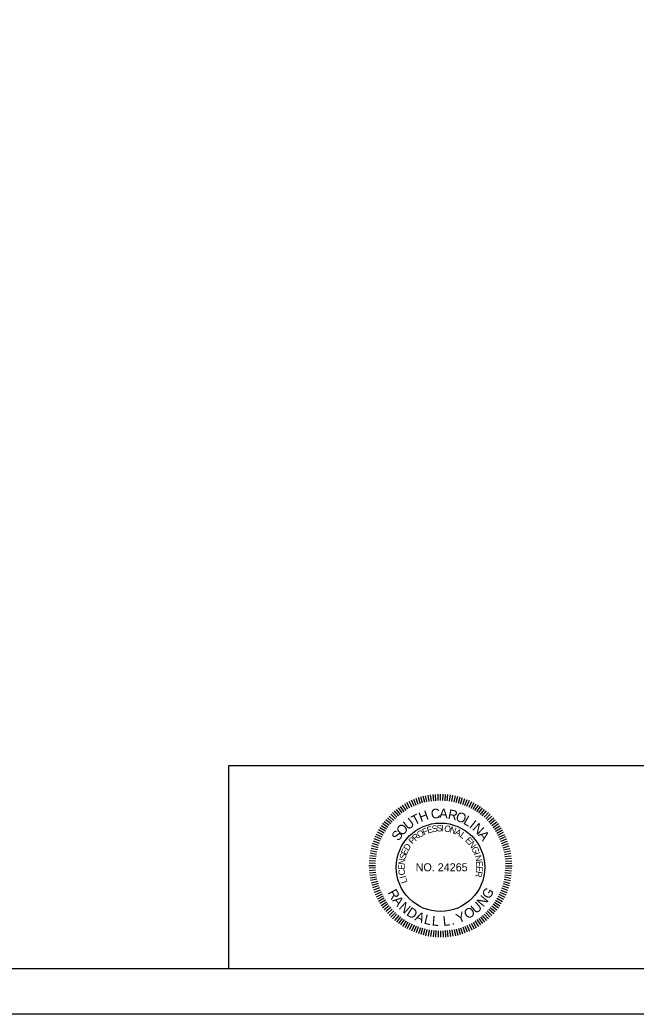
# Model space of a CAD drawing. Extents: x -796 to 2793, y -4650 to 4425.
# Drawn here: x 1879 to 2221, y -3500 to -2950 of the extents above; entities that cross this region are included whole.
import ezdxf

# ---------------------------------------------------------------- set-up
doc = ezdxf.new("R2010")
doc.units = 0
for name, color, linetype in [('RD_HC_CL', 7, 'Continuous'), ('RD_HC_Data', 7, 'Continuous'), ('RD_TX_PEShield', 7, 'Continuous')]:
    doc.layers.add(name, color=color, linetype=linetype)

msp = doc.modelspace()

# ---------------------------------------------------------------- linework, layer by layer
at = {"layer": 'RD_HC_CL'}
msp.add_lwpolyline([(981.4, -2400), (2777.4, -2400), (2777.4, -3500), (981.4, -3500)], close=True, dxfattribs=at)
at = {"layer": 'RD_HC_Data'}
for p, q in [((1995.01, -3362.55), (2757.6, -3362.55)), ((1995.01, -3475), (1995.01, -3362.55)), ((2760, -3500), (1000, -3500)), ((2760, -3500), (1000, -3500))]:
    msp.add_line(p, q, dxfattribs=at)
msp.add_lwpolyline([(1082.6, -2425), (2757.6, -2425), (2757.6, -3475), (1082.6, -3475)], close=True, dxfattribs=at)
at = {"layer": 'RD_TX_PEShield'}
for p, q in [((2096.52, -3385.54), (2094.96, -3382.34)), ((2096.52, -3385.54), (2094.96, -3382.34)), ((2097.64, -3384.97), (2096.19, -3381.71)), ((2097.64, -3384.97), (2096.19, -3381.71)), ((2098.81, -3384.52), (2097.48, -3381.22)), ((2098.81, -3384.52), (2097.48, -3381.22)), ((2099.98, -3384.07), (2098.77, -3380.72)), ((2099.98, -3384.07), (2098.77, -3380.72)), ((2101.16, -3383.62), (2100.06, -3380.23)), ((2101.16, -3383.62), (2100.06, -3380.23)), ((2102.37, -3383.29), (2101.39, -3379.87)), ((2102.37, -3383.29), (2101.39, -3379.87)), ((2103.59, -3382.96), (2102.73, -3379.51)), ((2103.59, -3382.96), (2102.73, -3379.51)), ((2104.8, -3382.64), (2104.06, -3379.16)), ((2104.8, -3382.64), (2104.06, -3379.16)), ((2106.05, -3382.44), (2105.43, -3378.94)), ((2106.05, -3382.44), (2105.43, -3378.94)), ((2107.29, -3382.25), (2106.79, -3378.72)), ((2107.29, -3382.25), (2106.79, -3378.72)), ((2108.53, -3382.05), (2108.16, -3378.51)), ((2108.53, -3382.05), (2108.16, -3378.51)), ((2109.79, -3381.98), (2109.54, -3378.44)), ((2109.79, -3381.98), (2109.54, -3378.44)), ((2111.04, -3381.92), (2110.92, -3378.36)), ((2111.04, -3381.92), (2110.92, -3378.36)), ((2112.3, -3381.85), (2112.3, -3378.29)), ((2112.3, -3381.85), (2112.3, -3378.29)), ((2113.55, -3381.92), (2113.68, -3378.36)), ((2113.55, -3381.92), (2113.68, -3378.36)), ((2114.81, -3381.98), (2115.06, -3378.44)), ((2114.81, -3381.98), (2115.06, -3378.44)), ((2116.07, -3382.05), (2116.44, -3378.51)), ((2116.07, -3382.05), (2116.44, -3378.51)), ((2117.31, -3382.25), (2117.8, -3378.72)), ((2117.31, -3382.25), (2117.8, -3378.72)), ((2118.55, -3382.44), (2119.17, -3378.94)), ((2118.55, -3382.44), (2119.17, -3378.94)), ((2119.79, -3382.64), (2120.53, -3379.16)), ((2119.79, -3382.64), (2120.53, -3379.16)), ((2119.79, -3382.64), (2120.53, -3379.16)), ((2121.01, -3382.96), (2121.87, -3379.51)), ((2121.01, -3382.96), (2121.87, -3379.51)), ((2121.01, -3382.96), (2121.87, -3379.51)), ((2122.22, -3383.29), (2123.2, -3379.87)), ((2122.22, -3383.29), (2123.2, -3379.87)), ((2122.22, -3383.29), (2123.2, -3379.87)), ((2123.44, -3383.62), (2124.54, -3380.23)), ((2123.44, -3383.62), (2124.54, -3380.23)), ((2123.44, -3383.62), (2124.54, -3380.23)), ((2124.61, -3384.07), (2125.83, -3380.72)), ((2124.61, -3384.07), (2125.83, -3380.72)), ((2124.61, -3384.07), (2125.83, -3380.72)), ((2125.78, -3384.52), (2127.12, -3381.22)), ((2125.78, -3384.52), (2127.12, -3381.22)), ((2125.78, -3384.52), (2127.12, -3381.22)), ((2126.96, -3384.97), (2128.41, -3381.71)), ((2126.96, -3384.97), (2128.41, -3381.71)), ((2126.96, -3384.97), (2128.41, -3381.71)), ((2128.08, -3385.54), (2129.64, -3382.34)), ((2128.08, -3385.54), (2129.64, -3382.34)), ((2128.08, -3385.54), (2129.64, -3382.34)), ((2089.16, -3390.32), (2086.87, -3387.59)), ((2089.16, -3390.32), (2086.87, -3387.59)), ((2090.13, -3389.53), (2087.94, -3386.72)), ((2090.13, -3389.53), (2087.94, -3386.72)), ((2091.11, -3388.73), (2089.02, -3385.85)), ((2091.11, -3388.73), (2089.02, -3385.85)), ((2092.17, -3388.05), (2090.18, -3385.1)), ((2092.17, -3388.05), (2090.18, -3385.1)), ((2093.22, -3387.37), (2091.34, -3384.35)), ((2093.22, -3387.37), (2091.34, -3384.35)), ((2094.28, -3386.68), (2092.5, -3383.6)), ((2094.28, -3386.68), (2092.5, -3383.6)), ((2095.4, -3386.11), (2093.73, -3382.97)), ((2095.4, -3386.11), (2093.73, -3382.97)), ((2129.2, -3386.11), (2130.87, -3382.97)), ((2129.2, -3386.11), (2130.87, -3382.97)), ((2129.2, -3386.11), (2130.87, -3382.97)), ((2130.32, -3386.68), (2132.1, -3383.6)), ((2130.32, -3386.68), (2132.1, -3383.6)), ((2130.32, -3386.68), (2132.1, -3383.6)), ((2131.38, -3387.37), (2133.26, -3384.35)), ((2131.38, -3387.37), (2133.26, -3384.35)), ((2131.38, -3387.37), (2133.26, -3384.35)), ((2132.43, -3388.05), (2134.42, -3385.1)), ((2132.43, -3388.05), (2134.42, -3385.1)), ((2132.43, -3388.05), (2134.42, -3385.1)), ((2133.48, -3388.73), (2135.58, -3385.85)), ((2133.48, -3388.73), (2135.58, -3385.85)), ((2133.48, -3388.73), (2135.58, -3385.85)), ((2134.46, -3389.53), (2136.65, -3386.72)), ((2134.46, -3389.53), (2136.65, -3386.72)), ((2134.46, -3389.53), (2136.65, -3386.72)), ((2135.44, -3390.32), (2137.72, -3387.59)), ((2135.44, -3390.32), (2137.72, -3387.59)), ((2135.44, -3390.32), (2137.72, -3387.59)), ((2084.72, -3394.75), (2082, -3392.47)), ((2084.72, -3394.75), (2082, -3392.47)), ((2085.51, -3393.78), (2082.87, -3391.4)), ((2085.51, -3393.78), (2082.87, -3391.4)), ((2086.4, -3392.89), (2083.84, -3390.42)), ((2086.4, -3392.89), (2083.84, -3390.42)), ((2087.29, -3392), (2084.82, -3389.44)), ((2087.29, -3392), (2084.82, -3389.44)), ((2088.18, -3391.11), (2085.8, -3388.46)), ((2088.18, -3391.11), (2085.8, -3388.46)), ((2136.42, -3391.11), (2138.8, -3388.46)), ((2136.42, -3391.11), (2138.8, -3388.46)), ((2136.42, -3391.11), (2138.8, -3388.46)), ((2137.31, -3392), (2139.78, -3389.44)), ((2137.31, -3392), (2139.78, -3389.44)), ((2137.31, -3392), (2139.78, -3389.44)), ((2138.2, -3392.89), (2140.75, -3390.42)), ((2138.2, -3392.89), (2140.75, -3390.42)), ((2138.2, -3392.89), (2140.75, -3390.42)), ((2139.08, -3393.78), (2141.73, -3391.4)), ((2139.08, -3393.78), (2141.73, -3391.4)), ((2139.08, -3393.78), (2141.73, -3391.4)), ((2139.88, -3394.75), (2142.6, -3392.47)), ((2139.88, -3394.75), (2142.6, -3392.47)), ((2139.88, -3394.75), (2142.6, -3392.47)), ((2081.08, -3399.87), (2078, -3398.09)), ((2081.08, -3399.87), (2078, -3398.09)), ((2081.77, -3398.82), (2078.75, -3396.93)), ((2081.77, -3398.82), (2078.75, -3396.93)), ((2082.45, -3397.76), (2079.5, -3395.78)), ((2082.45, -3397.76), (2079.5, -3395.78)), ((2083.14, -3396.71), (2080.26, -3394.62)), ((2083.14, -3396.71), (2080.26, -3394.62)), ((2083.93, -3395.73), (2081.13, -3393.54)), ((2083.93, -3395.73), (2081.13, -3393.54)), ((2140.67, -3395.73), (2143.47, -3393.54)), ((2140.67, -3395.73), (2143.47, -3393.54)), ((2140.67, -3395.73), (2143.47, -3393.54)), ((2141.46, -3396.71), (2144.34, -3394.62)), ((2141.46, -3396.71), (2144.34, -3394.62)), ((2141.46, -3396.71), (2144.34, -3394.62)), ((2142.14, -3397.76), (2145.09, -3395.78)), ((2142.14, -3397.76), (2145.09, -3395.78)), ((2142.14, -3397.76), (2145.09, -3395.78)), ((2142.83, -3398.82), (2145.84, -3396.93)), ((2142.83, -3398.82), (2145.84, -3396.93)), ((2142.83, -3398.82), (2145.84, -3396.93)), ((2143.51, -3399.87), (2146.6, -3398.09)), ((2143.51, -3399.87), (2146.6, -3398.09)), ((2143.51, -3399.87), (2146.6, -3398.09)), ((2078.47, -3405.58), (2075.13, -3404.37)), ((2078.47, -3405.58), (2075.13, -3404.37)), ((2078.92, -3404.41), (2075.62, -3403.08)), ((2078.92, -3404.41), (2075.62, -3403.08)), ((2079.37, -3403.24), (2076.12, -3401.79)), ((2079.37, -3403.24), (2076.12, -3401.79)), ((2079.94, -3402.11), (2076.74, -3400.56)), ((2079.94, -3402.11), (2076.74, -3400.56)), ((2080.51, -3400.99), (2077.37, -3399.33)), ((2080.51, -3400.99), (2077.37, -3399.33)), ((2144.09, -3400.99), (2147.22, -3399.33)), ((2144.09, -3400.99), (2147.22, -3399.33)), ((2144.09, -3400.99), (2147.22, -3399.33)), ((2144.66, -3402.11), (2147.85, -3400.56)), ((2144.66, -3402.11), (2147.85, -3400.56)), ((2144.66, -3402.11), (2147.85, -3400.56)), ((2145.23, -3403.24), (2148.48, -3401.79)), ((2145.23, -3403.24), (2148.48, -3401.79)), ((2145.23, -3403.24), (2148.48, -3401.79)), ((2145.68, -3404.41), (2148.97, -3403.08)), ((2145.68, -3404.41), (2148.97, -3403.08)), ((2145.68, -3404.41), (2148.97, -3403.08)), ((2146.13, -3405.58), (2149.47, -3404.37)), ((2146.13, -3405.58), (2149.47, -3404.37)), ((2146.13, -3405.58), (2149.47, -3404.37)), ((2077.04, -3410.4), (2073.56, -3409.66)), ((2077.04, -3410.4), (2073.56, -3409.66)), ((2077.37, -3409.19), (2073.92, -3408.33)), ((2077.37, -3409.19), (2073.92, -3408.33)), ((2077.69, -3407.97), (2074.27, -3406.99)), ((2077.69, -3407.97), (2074.27, -3406.99)), ((2078.02, -3406.76), (2074.63, -3405.66)), ((2078.02, -3406.76), (2074.63, -3405.66)), ((2146.58, -3406.76), (2149.96, -3405.66)), ((2146.58, -3406.76), (2149.96, -3405.66)), ((2146.58, -3406.76), (2149.96, -3405.66)), ((2146.9, -3407.97), (2150.32, -3406.99)), ((2146.9, -3407.97), (2150.32, -3406.99)), ((2146.9, -3407.97), (2150.32, -3406.99)), ((2147.23, -3409.19), (2150.68, -3408.33)), ((2147.23, -3409.19), (2150.68, -3408.33)), ((2147.23, -3409.19), (2150.68, -3408.33)), ((2147.56, -3410.4), (2151.04, -3409.66)), ((2147.56, -3410.4), (2151.04, -3409.66)), ((2147.56, -3410.4), (2151.04, -3409.66)), ((2076.38, -3415.38), (2072.84, -3415.14)), ((2076.38, -3415.38), (2072.84, -3415.14)), ((2076.45, -3414.13), (2072.91, -3413.76)), ((2076.45, -3414.13), (2072.91, -3413.76)), ((2076.65, -3412.89), (2073.13, -3412.39)), ((2076.65, -3412.89), (2073.13, -3412.39)), ((2076.84, -3411.64), (2073.34, -3411.03)), ((2076.84, -3411.64), (2073.34, -3411.03)), ((2147.75, -3411.64), (2151.25, -3411.03)), ((2147.75, -3411.64), (2151.25, -3411.03)), ((2147.75, -3411.64), (2151.25, -3411.03)), ((2147.95, -3412.89), (2151.47, -3412.39)), ((2147.95, -3412.89), (2151.47, -3412.39)), ((2147.95, -3412.89), (2151.47, -3412.39)), ((2148.15, -3414.13), (2151.69, -3413.76)), ((2148.15, -3414.13), (2151.69, -3413.76)), ((2148.15, -3414.13), (2151.69, -3413.76)), ((2148.21, -3415.38), (2151.76, -3415.14)), ((2148.21, -3415.38), (2151.76, -3415.14)), ((2148.21, -3415.38), (2151.76, -3415.14)), ((2076.25, -3417.9), (2072.69, -3417.9)), ((2076.25, -3417.9), (2072.69, -3417.9)), ((2076.32, -3416.64), (2072.77, -3416.52)), ((2076.32, -3416.64), (2072.77, -3416.52)), ((2076.32, -3419.15), (2072.77, -3419.28)), ((2076.32, -3419.15), (2072.77, -3419.28)), ((2076.38, -3420.41), (2072.84, -3420.66)), ((2076.38, -3420.41), (2072.84, -3420.66)), ((2148.08, -3420.4), (2151.61, -3420.65)), ((2148.08, -3420.4), (2151.61, -3420.65)), ((2148.21, -3419.15), (2151.76, -3419.27)), ((2148.21, -3419.15), (2151.76, -3419.27)), ((2148.28, -3416.64), (2151.83, -3416.52)), ((2148.28, -3416.64), (2151.83, -3416.52)), ((2148.28, -3416.64), (2151.83, -3416.52)), ((2148.34, -3417.9), (2151.9, -3417.9)), ((2148.34, -3417.9), (2151.9, -3417.9)), ((2148.34, -3417.9), (2151.9, -3417.9)), ((2076.45, -3421.66), (2072.91, -3422.04)), ((2076.45, -3421.66), (2072.91, -3422.04)), ((2076.65, -3422.91), (2073.13, -3423.4)), ((2076.65, -3422.91), (2073.13, -3423.4)), ((2076.84, -3424.15), (2073.34, -3424.76)), ((2076.84, -3424.15), (2073.34, -3424.76)), ((2077.04, -3425.39), (2073.56, -3426.13)), ((2077.04, -3425.39), (2073.56, -3426.13)), ((2147.56, -3425.39), (2151.04, -3426.13)), ((2147.56, -3425.39), (2151.04, -3426.13)), ((2147.69, -3424.14), (2151.18, -3424.75)), ((2147.69, -3424.14), (2151.18, -3424.75)), ((2147.82, -3422.89), (2151.33, -3423.38)), ((2147.82, -3422.89), (2151.33, -3423.38)), ((2147.95, -3421.64), (2151.47, -3422.01)), ((2147.95, -3421.64), (2151.47, -3422.01)), ((2077.37, -3426.61), (2073.92, -3427.47)), ((2077.37, -3426.61), (2073.92, -3427.47)), ((2077.69, -3427.82), (2074.27, -3428.8)), ((2077.69, -3427.82), (2074.27, -3428.8)), ((2078.02, -3429.03), (2074.63, -3430.13)), ((2078.47, -3430.21), (2075.13, -3431.43)), ((2078.47, -3430.21), (2075.13, -3431.43)), ((2078.92, -3431.38), (2075.62, -3432.71)), ((2078.92, -3431.38), (2075.62, -3432.71)), ((2145.68, -3431.38), (2148.97, -3432.71)), ((2145.68, -3431.38), (2148.97, -3432.71)), ((2146.13, -3430.21), (2149.47, -3431.43)), ((2146.13, -3430.21), (2149.47, -3431.43)), ((2146.58, -3429.03), (2149.96, -3430.13)), ((2146.58, -3429.03), (2149.96, -3430.13)), ((2146.9, -3427.82), (2150.32, -3428.8)), ((2146.9, -3427.82), (2150.32, -3428.8)), ((2147.23, -3426.61), (2150.68, -3427.47)), ((2147.23, -3426.61), (2150.68, -3427.47)), ((2079.37, -3432.56), (2076.12, -3434)), ((2079.37, -3432.56), (2076.12, -3434)), ((2079.94, -3433.68), (2076.74, -3435.24)), ((2079.94, -3433.68), (2076.74, -3435.24)), ((2080.51, -3434.8), (2077.37, -3436.47)), ((2080.51, -3434.8), (2077.37, -3436.47)), ((2081.08, -3435.92), (2078, -3437.7)), ((2081.08, -3435.92), (2078, -3437.7)), ((2081.77, -3436.97), (2078.75, -3438.86)), ((2081.77, -3436.97), (2078.75, -3438.86)), ((2142.83, -3436.97), (2145.84, -3438.86)), ((2142.83, -3436.97), (2145.84, -3438.86)), ((2143.51, -3435.92), (2146.6, -3437.7)), ((2143.51, -3435.92), (2146.6, -3437.7)), ((2144.09, -3434.8), (2147.22, -3436.47)), ((2144.09, -3434.8), (2147.22, -3436.47)), ((2144.66, -3433.68), (2147.85, -3435.24)), ((2144.66, -3433.68), (2147.85, -3435.24)), ((2145.23, -3432.56), (2148.48, -3434)), ((2145.23, -3432.56), (2148.48, -3434)), ((2082.45, -3438.03), (2079.5, -3440.02)), ((2082.45, -3438.03), (2079.5, -3440.02)), ((2083.14, -3439.08), (2080.26, -3441.18)), ((2083.14, -3439.08), (2080.26, -3441.18)), ((2083.93, -3440.06), (2081.13, -3442.25)), ((2083.93, -3440.06), (2081.13, -3442.25)), ((2084.72, -3441.04), (2082, -3443.32)), ((2084.72, -3441.04), (2082, -3443.32)), ((2085.51, -3442.01), (2082.87, -3444.4)), ((2085.51, -3442.01), (2082.87, -3444.4)), ((2086.4, -3442.9), (2083.84, -3445.37)), ((2086.4, -3442.9), (2083.84, -3445.37)), ((2138.2, -3442.9), (2140.75, -3445.37)), ((2138.2, -3442.9), (2140.75, -3445.37)), ((2139.08, -3442.01), (2141.73, -3444.4)), ((2139.08, -3442.01), (2141.73, -3444.4)), ((2139.88, -3441.04), (2142.6, -3443.32)), ((2139.88, -3441.04), (2142.6, -3443.32)), ((2140.67, -3440.06), (2143.47, -3442.25)), ((2140.67, -3440.06), (2143.47, -3442.25)), ((2141.46, -3439.08), (2144.34, -3441.18)), ((2141.46, -3439.08), (2144.34, -3441.18)), ((2142.14, -3438.03), (2145.09, -3440.02)), ((2142.14, -3438.03), (2145.09, -3440.02)), ((2087.29, -3443.79), (2084.82, -3446.35)), ((2087.29, -3443.79), (2084.82, -3446.35)), ((2088.18, -3444.68), (2085.8, -3447.33)), ((2088.18, -3444.68), (2085.8, -3447.33)), ((2089.16, -3445.47), (2086.87, -3448.2)), ((2089.16, -3445.47), (2086.87, -3448.2)), ((2090.13, -3446.27), (2087.94, -3449.07)), ((2090.13, -3446.27), (2087.94, -3449.07)), ((2091.11, -3447.06), (2089.02, -3449.94)), ((2091.11, -3447.06), (2089.02, -3449.94)), ((2092.17, -3447.74), (2090.18, -3450.69)), ((2092.17, -3447.74), (2090.18, -3450.69)), ((2093.22, -3448.43), (2091.34, -3451.44)), ((2093.22, -3448.43), (2091.34, -3451.44)), ((2131.38, -3448.43), (2133.26, -3451.44)), ((2131.38, -3448.43), (2133.26, -3451.44)), ((2132.43, -3447.74), (2134.42, -3450.69)), ((2132.43, -3447.74), (2134.42, -3450.69)), ((2133.48, -3447.06), (2135.58, -3449.94)), ((2133.48, -3447.06), (2135.58, -3449.94)), ((2134.46, -3446.27), (2136.65, -3449.07)), ((2134.46, -3446.27), (2136.65, -3449.07)), ((2135.44, -3445.47), (2137.72, -3448.2)), ((2135.44, -3445.47), (2137.72, -3448.2)), ((2136.42, -3444.68), (2138.8, -3447.33)), ((2137.31, -3443.79), (2139.78, -3446.35)), ((2137.31, -3443.79), (2139.78, -3446.35)), ((2094.28, -3449.11), (2092.5, -3452.19)), ((2094.28, -3449.11), (2092.5, -3452.19)), ((2095.4, -3449.68), (2093.73, -3452.82)), ((2095.4, -3449.68), (2093.73, -3452.82)), ((2096.52, -3450.25), (2094.96, -3453.45)), ((2096.52, -3450.25), (2094.96, -3453.45)), ((2097.64, -3450.82), (2096.19, -3454.08)), ((2097.64, -3450.82), (2096.19, -3454.08)), ((2098.81, -3451.28), (2097.48, -3454.57)), ((2098.81, -3451.28), (2097.48, -3454.57)), ((2099.98, -3451.73), (2098.77, -3455.07)), ((2099.98, -3451.73), (2098.77, -3455.07)), ((2101.16, -3452.18), (2100.06, -3455.56)), ((2101.16, -3452.18), (2100.06, -3455.56)), ((2102.37, -3452.5), (2101.39, -3455.92)), ((2102.37, -3452.5), (2101.39, -3455.92)), ((2103.59, -3452.83), (2102.73, -3456.28)), ((2103.59, -3452.83), (2102.73, -3456.28)), ((2104.8, -3453.15), (2104.06, -3456.64)), ((2104.8, -3453.15), (2104.06, -3456.64)), ((2106.05, -3453.35), (2105.43, -3456.85)), ((2106.05, -3453.35), (2105.43, -3456.85)), ((2107.29, -3453.55), (2106.79, -3457.07)), ((2107.29, -3453.55), (2106.79, -3457.07)), ((2108.53, -3453.74), (2108.16, -3457.28)), ((2108.53, -3453.74), (2108.16, -3457.28)), ((2109.79, -3453.81), (2109.54, -3457.36)), ((2109.79, -3453.81), (2109.54, -3457.36)), ((2111.04, -3453.88), (2110.92, -3457.43)), ((2111.04, -3453.88), (2110.92, -3457.43)), ((2112.3, -3453.94), (2112.3, -3457.5)), ((2112.3, -3453.94), (2112.3, -3457.5)), ((2113.55, -3453.88), (2113.68, -3457.43)), ((2113.55, -3453.88), (2113.68, -3457.43)), ((2114.81, -3453.81), (2115.06, -3457.36)), ((2114.81, -3453.81), (2115.06, -3457.36)), ((2116.07, -3453.74), (2116.44, -3457.28)), ((2116.07, -3453.74), (2116.44, -3457.28)), ((2117.31, -3453.55), (2117.8, -3457.07)), ((2117.31, -3453.55), (2117.8, -3457.07)), ((2118.55, -3453.35), (2119.17, -3456.85)), ((2118.55, -3453.35), (2119.17, -3456.85)), ((2119.79, -3453.15), (2120.53, -3456.64)), ((2119.79, -3453.15), (2120.53, -3456.64)), ((2121.01, -3452.83), (2121.87, -3456.28)), ((2121.01, -3452.83), (2121.87, -3456.28)), ((2122.22, -3452.5), (2123.2, -3455.92)), ((2122.22, -3452.5), (2123.2, -3455.92)), ((2123.44, -3452.18), (2124.54, -3455.56)), ((2123.44, -3452.18), (2124.54, -3455.56)), ((2124.61, -3451.73), (2125.83, -3455.07)), ((2124.61, -3451.73), (2125.83, -3455.07)), ((2125.78, -3451.28), (2127.12, -3454.57)), ((2125.78, -3451.28), (2127.12, -3454.57)), ((2126.96, -3450.82), (2128.41, -3454.08)), ((2126.96, -3450.82), (2128.41, -3454.08)), ((2128.08, -3450.25), (2129.64, -3453.45)), ((2128.08, -3450.25), (2129.64, -3453.45)), ((2129.2, -3449.68), (2130.87, -3452.82)), ((2129.2, -3449.68), (2130.87, -3452.82)), ((2130.32, -3449.11), (2132.1, -3452.19)), ((2130.32, -3449.11), (2132.1, -3452.19))]:
    msp.add_line(p, q, dxfattribs=at)
msp.add_circle((2112.3, -3418.77), 24.48, dxfattribs=at)

# ---------------------------------------------------------------- texts
for s, height, rotation, p in [('H', 5.34, 19.9102, (2101.39, -3393.85)), ('C', 5.34, 6.8832, (2107.29, -3392.04)), ('A', 5.34, 357.9448, (2111.51, -3391.58)), ('R', 5.34, 348.267, (2116.09, -3391.84)), ('U', 5.34, 37.7726, (2094.28, -3398.4)), ('T', 5.34, 28.0947, (2097.96, -3395.66)), ('O', 5.34, 339.3286, (2120.23, -3392.75)), ('L', 5.34, 329.6507, (2124.49, -3394.46)), ('I', 5.34, 321.4663, (2127.83, -3396.44)), ('S', 5.34, 54.9027, (2089.07, -3404.61)), ('O', 5.34, 47.4504, (2091.11, -3401.72)), ('O', 3.56, 31.7869, (2100.54, -3402.71)), ('F', 3.56, 23.0853, (2103.11, -3401.12)), ('E', 3.56, 16.1843, (2105.3, -3400.14)), ('S', 3.56, 8.6909, (2107.79, -3399.39)), ('S', 3.56, 1.79, (2110.15, -3398.98)), ('I', 3.56, 354.889, (2112.54, -3398.87)), ('O', 3.56, 350.4045, (2114.1, -3398.95)), ('N', 3.56, 341.7029, (2117.08, -3399.45)), ('A', 3.56, 333.0013, (2119.94, -3400.4)), ('N', 5.34, 317.0007, (2129.52, -3397.72)), ('P', 3.56, 46.7912, (2096.78, -3406.3)), ('R', 3.56, 39.8902, (2098.4, -3404.53)), ('L', 3.56, 324.2997, (2122.64, -3401.76)), ('E', 3.56, 313.2251, (2125.71, -3404.07)), ('N', 3.56, 305.7317, (2127.52, -3405.94)), ('A', 5.34, 307.3229, (2132.81, -3400.91)), ('E', 3.56, 66.5674, (2093.48, -3412.29)), ('D', 3.56, 59.074, (2094.49, -3409.89)), ('G', 3.56, 297.0301, (2129.28, -3408.39)), ('N', 3.56, 82.17, (2092.43, -3417.59)), ('S', 3.56, 73.4683, (2092.84, -3414.59)), ('I', 3.56, 288.3285, (2130.66, -3411.08)), ('N', 3.56, 283.8441, (2131.2, -3412.54)), ('E', 3.56, 89.6633, (2092.44, -3420.19)), ('C', 3.56, 97.7667, (2092.84, -3422.97)), ('E', 3.56, 275.1424, (2131.93, -3415.47)), ('E', 3.56, 267.6491, (2132.19, -3418.06)), ('I', 3.56, 102.2511, (2093.23, -3424.48)), ('L', 3.56, 109.7445, (2094.13, -3426.92)), ('R', 3.56, 260.1557, (2132.11, -3420.66)), ('R', 5.34, 299.1493, (2082.9, -3432.75)), ('G', 5.34, 60.1113, (2139.41, -3436.8)), ('A', 5.34, 308.0877, (2085.42, -3437.15)), ('N', 5.34, 50.4335, (2135.99, -3441.1)), ('N', 5.34, 317.7655, (2088.89, -3441.4)), ('D', 5.34, 327.4433, (2093.03, -3445.01)), ('O', 5.34, 31.0778, (2127.25, -3447.69)), ('U', 5.34, 40.7556, (2131.9, -3444.76)), ('A', 5.34, 337.1212, (2097.72, -3447.88)), ('L', 5.34, 346.799, (2102.82, -3449.92)), ('L', 5.34, 354.9835, (2107.35, -3450.95)), ('L', 5.34, 6.5171, (2113.88, -3451.29)), ('Y', 5.34, 21.4, (2122.18, -3449.79)), ('.', 5.34, 14.7016, (2118.49, -3450.73))]:
    msp.add_text(s, height=height, rotation=rotation, dxfattribs=at).set_placement(p)
msp.add_text('NO. 24265', height=4.45, dxfattribs=at).set_placement((2098.54, -3421))

doc.saveas('drawing.dxf')
